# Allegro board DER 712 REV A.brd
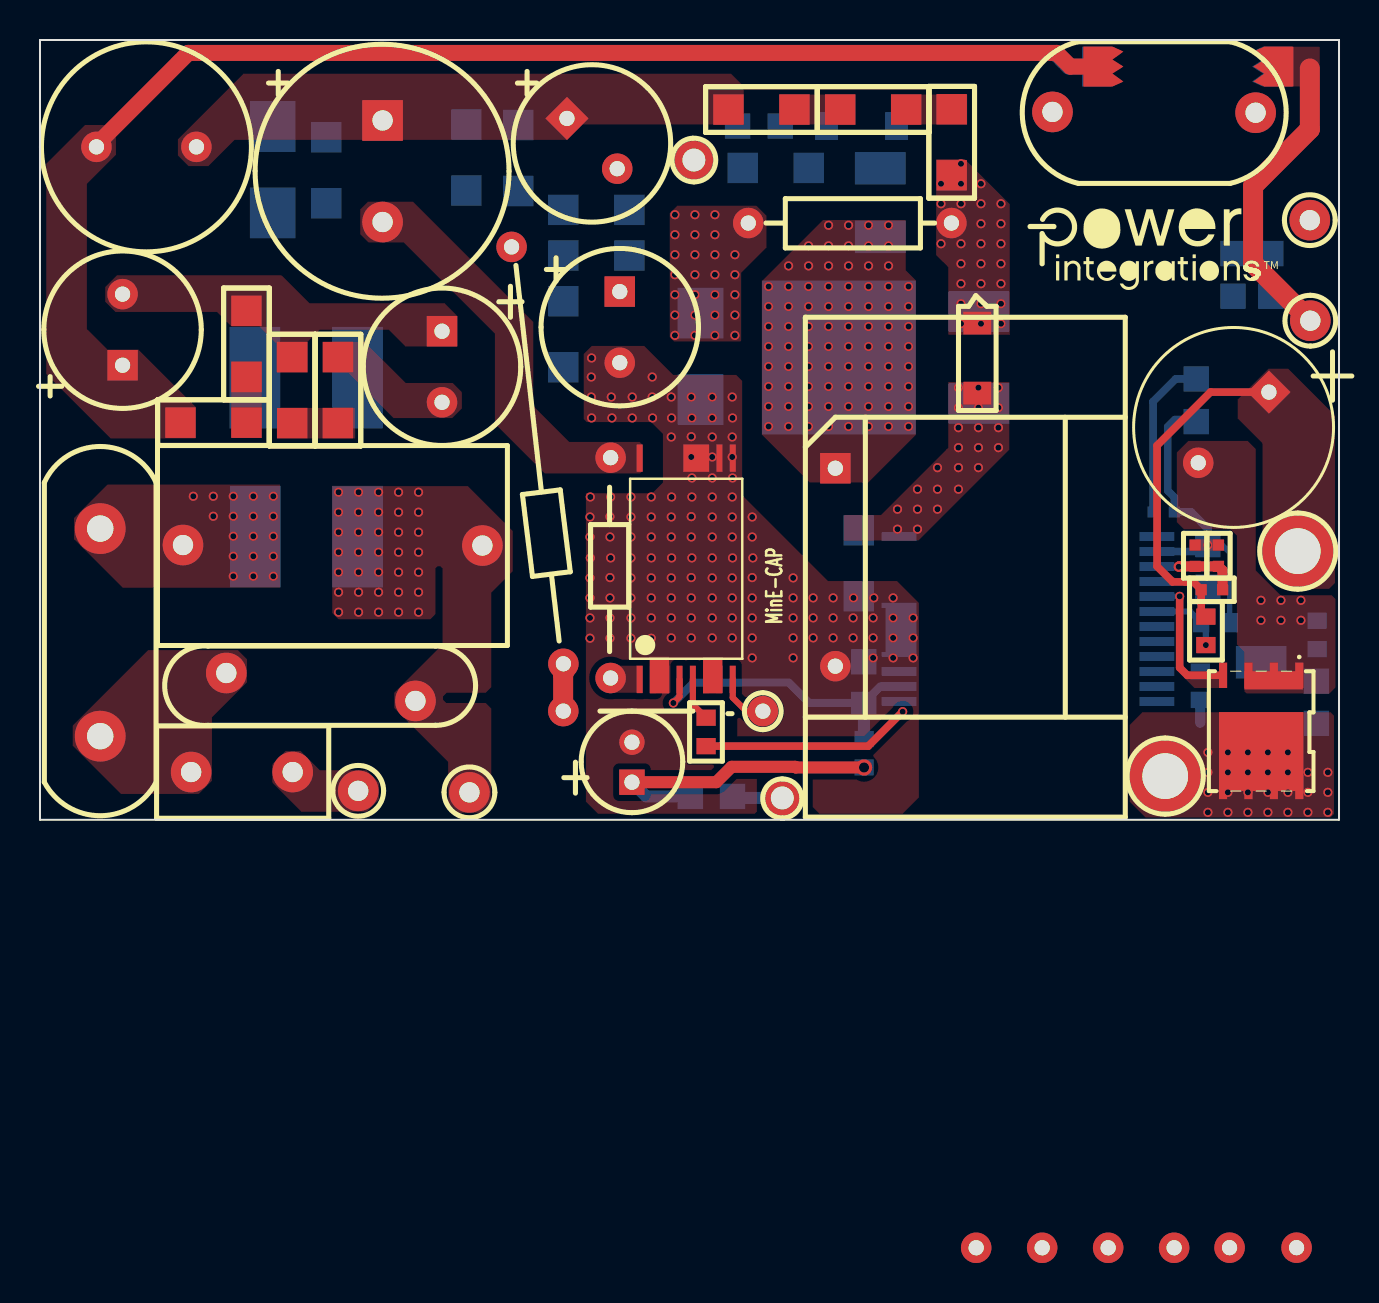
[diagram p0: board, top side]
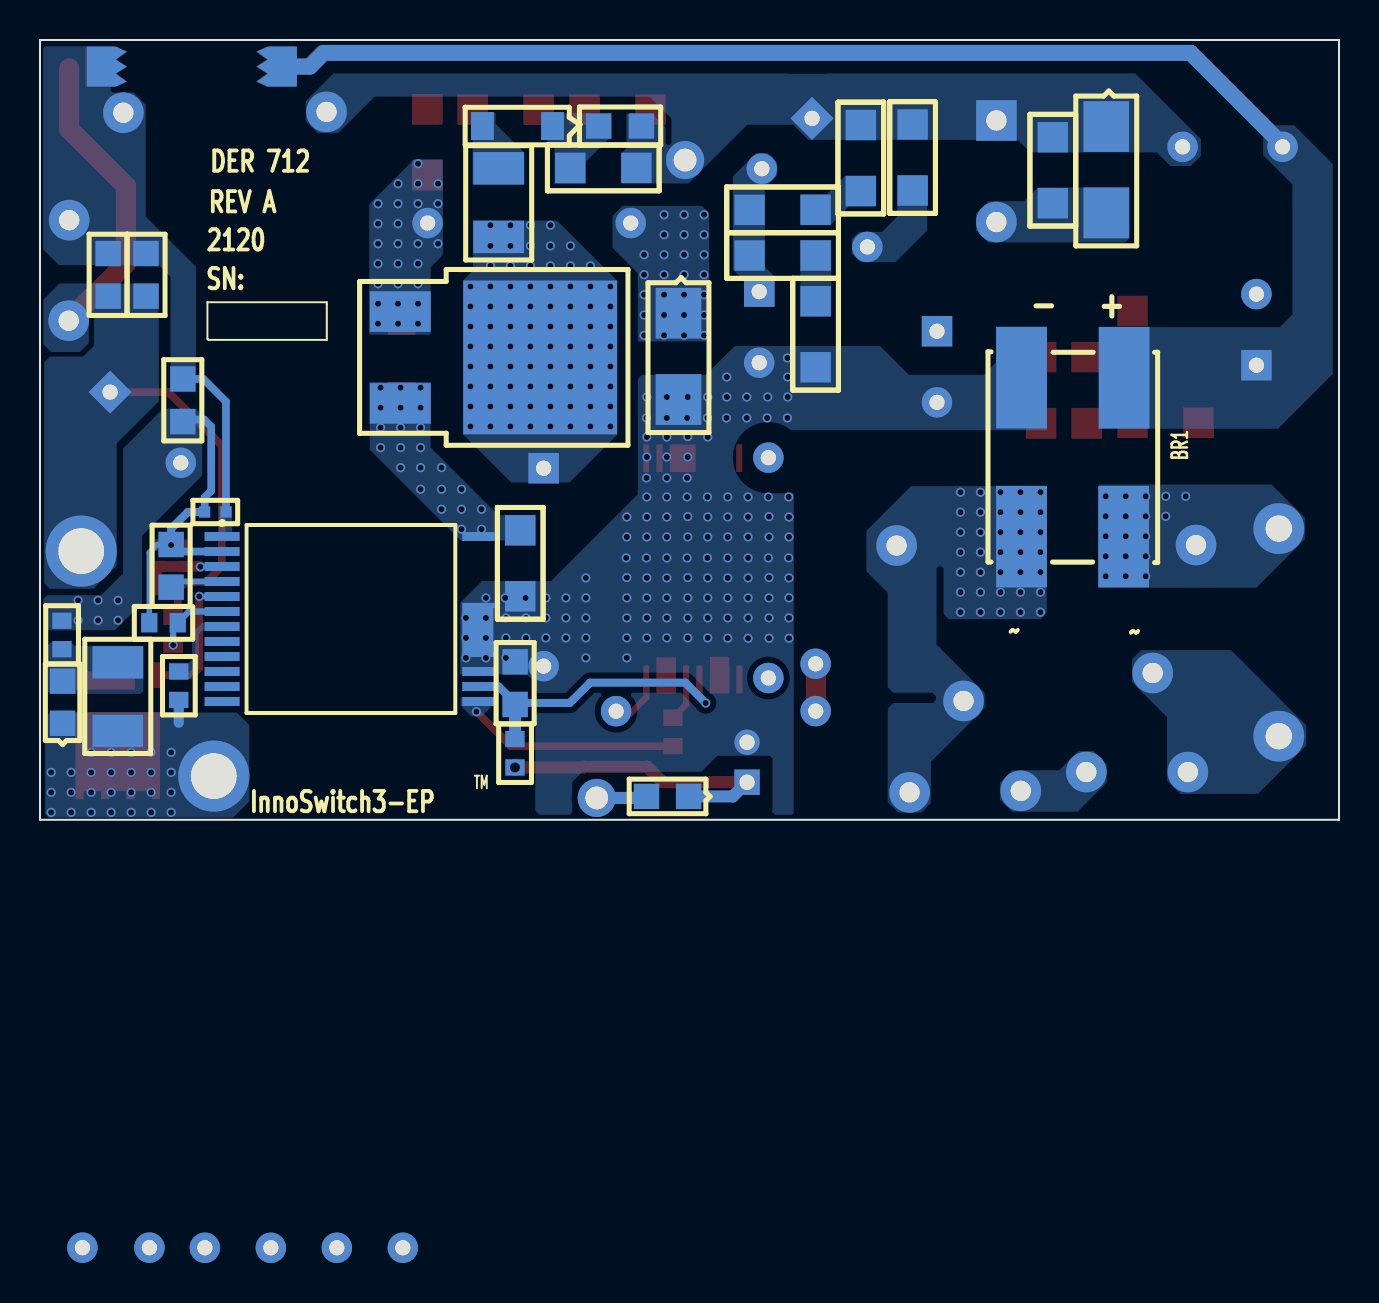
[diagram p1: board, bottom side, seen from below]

Outline 64.97 x 39 mm; copper layers: TOP, BOTTOM. Coordinates in mm from the lower left corner of the outline.
Outline path: 0,39 0,0 64.97,0 64.97,39 0,39

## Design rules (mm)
constraint set DEFAULT: min track width 0.508

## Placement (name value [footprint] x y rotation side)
BR1  Z4DGP410L-HF  [PI_SM_D_Z4D]  10.77 22.16 180 bottom
C1  0.1 uF  [PI_NP_CAP_RAD_17P5X10XLS15D040]  7.13 13.72 0 top
C2  22 uF  [PIPOLCAPCLYD320LS140030]  4.13 22.73 90 top
C3  1 nF  [PINPYCAPRAD540X290LS400040]  50.64 36.65 0 top
C4  1000 pF  [PISMC0805]  34.89 34.7 0 bottom
C6  4.7 uF  [PISMC0805]  41.21 5.77 90 bottom
C7  1000 pF  [PISMC0603]  63.87 8.53 90 bottom
C8  1000 uF  [PIPOLCAPCLYD10MMD30]  61.46 21.39 225 top
C10  2.2 uF  [PISMC0805]  58.41 11.63 90 bottom
C11  1 uF  [PISMC0603]  59.5 9.86 180 bottom
C12  1000 pF  [PISMR0402]  56.73 15.39 180 bottom
C13  1000 pF  [PISMR0402]  57.77 13.74 270 top
C16  10 uF  [PISMC0805]  61.56 26.19 90 bottom
C17  10 uF  [PISMC0805]  59.67 26.19 90 bottom
C18  22 uF  [PIPOLCAPCLYD320LS140030]  26.35 35.08 315 top
C19  82 uF  [PIPOLCAPCLYD500LS200040]  17.13 34.98 270 top
C21  22 uF  [PIPOLCAPCLYD200LS80030]  29.61 1.88 90 top
C24  22 uF  [PIPOLCAPCLYD320LS140030]  20.11 24.43 270 top
C25  22 uF  [PIPOLCAPCLYD320LS140030]  29 26.42 270 top
C27  22 pF  [PISMC1206]  40.95 14.48 270 bottom
D1  SM4007PL-TP  [PI_SM_SOD-123_12]  39.33 34.7 0 bottom
D2  BAV20WS-7-F  [PISMDSOD323]  32.53 1.17 0 bottom
D4  BAV20WS-7-F  [PISMDSOD323]  63.84 4.83 90 bottom
F1  5 A  [PI_RST_MICROFUSE]  12.64 2.39 180 top
FL1  Hole_70mils  [PI_HOLE_70MIL]  62.91 13.41 0 top
FL2  Hole_70mils  [PI_HOLE_70MIL]  56.28 2.16 0 top
FL3  Hole_30mils  [PI_HOLE_30MIL]  37.12 1.09 0 top
FL4  Hole_30mils  [PI_HOLE_30MIL]  32.7 32.99 0 top
GND  BLK  [PITPKEYSTONE100X100]  63.51 29.99 270 top
L  BLK  [PITPKEYSTONE100X100]  15.92 1.45 90 top
L1  220 uH  [PICHOKE10P5X14P5D030]  5.32 33.66 0 top
N  WHT  [PITPKEYSTONE100X100]  21.48 1.37 90 top
NOREF  -  []  -223.63 -144.78 0 top
NOREF#2  -  []  0 0 0 top
NOREF#3  -  []  49.47 30.38 0 top
NOREF#4  -  []  -145.82 54.23 0 top
NOREF#5  -  []  0 0 90 top
Q2  AON6220  [PISMPQFN5X6B]  62.98 7.23 180 top
Q3  STD15N50M2AG  [PISMDDPAK]  46.95 25.42 270 bottom
R3  1.6 M  [PI18WVRESD80LS100D030#2]  23.59 28.65 270 top
R5  20  [PISMR1210]  42.03 32.58 270 bottom
R7  470 k  [PISMR1206]  35.14 32.6 0 bottom
R8  4.7 k  [PISMR0603]  41.21 2.62 90 bottom
R11  8.2  [PISMR1210]  61.08 4.45 90 bottom
R12  47  [PISMR0603]  58.03 5.99 90 bottom
R15  100.0 k  [PISMR0402]  58.08 11.51 0 top
R16  5.62 k  [PISMR0402]  58.94 12.67 90 top
R24  3.9 M  [PISMR1206]  14.32 34.14 270 bottom
R27  1.3 M  [PI18WVRESD80LS100D030]  28.54 20.11 270 top
R28  10  [PI14WVRESD100LS100D030]  45.58 29.84 180 top
R29  1.6 M  [PISMR1206]  21.33 34.77 270 bottom
R30  1 M  [PISMR1206]  45.6 35.53 270 top
R31  1 M  [PISMR1206]  40.02 35.52 0 top
R32  1 M  [PISMR1206]  34.43 35.52 0 top
R33  0.012  [PISMR0805]  57.83 22.05 270 bottom
R34  10 M  [PISMR1206]  7.03 19.86 0 top
R35  10 M  [PISMR1206]  10.33 22.15 90 top
R36  10 M  [PISMR1206]  12.61 23.14 270 top
R37  10 M  [PISMR1206]  14.9 19.84 90 top
R38  10 M  [PISMR1206]  23.92 34.75 270 bottom
R39  10 M  [PISMR1206]  26.18 30.51 0 bottom
R40  10 M  [PISMR1206]  29.48 28.22 180 bottom
R41  10 M  [PISMR1206]  26.18 25.93 270 bottom
R42  20 k  [PISMR0603]  33.31 5.11 270 top
R43  1.6 M  [PI18WVRESD80LS100D030#3]  27.66 5.44 0 top
R44  100  [PISMR0603]  58.31 8.74 90 top
RT1  10  [PI_RAD770X220LS330D052]  3.01 13.56 270 top
RV1  440 VAC  [PIDISC610X212LS295X95040]  10.3 7.85 0 top
SG1  6.5 mm gap  [PI_SPARK_GAP_6P5MM]  57.37 37.67 0 bottom
SG2  6.5 mm gap  [PI_SPARK_GAP_6P5MM]  57.43 37.67 0 top
T2  ATQ25/16  [PI_BOBBIN_ATQ25_H_8P]  46.28 12.63 0 top
U1  INN3679C-H606  [PI_IC_INSOP_24D]  55.86 14.17 180 bottom
U4  MIN1072M  [PI_SM_MINSOP16A_1]  29.99 7.02 0 top
UNK24V  RED  [PITPKEYSTONE100X100]  63.53 24.96 0 top
VR1  MMSZ5246B-7-F  [PI_SM_SOD-123_12]  46.88 24.84 270 top
VR2  SMAJ400A  [PISMDO214AC12]  33.03 25.34 270 bottom
VR4  BZG03C200-M3-08  [PISMDO214AC12]  11.64 34.67 270 bottom

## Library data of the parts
BR1 = DISCRETE BRIDGE_+~~-
C1 = CAP NP: alternate symbols: (pi_np_cap_rad_17p5x10xLS15d040H)
C2 C18 C24 C25 = CAP POL: alternate symbols: (pipolcapclyd320ls140030h630)
C3 = CAP NP: alternate symbols: (pinpycaprad540x290ls400040h,pinpycaprad500x220ls400040)
C4 C6 C7 C10 C27 = CAP NP
C8 = CAP POL: alternate symbols: (pipolcapclyd10x18mmD30H)
C11 = CAP NP: alternate symbols: (pismc0603_1)
C12 C13 = CAP NP: alternate symbols: (pismr0402_1); room: 2
C16 C17 = CAP NP: alternate symbols: (pismc0805_1)
C19 = CAP POL: alternate symbols: (pipolcapclyd500ls200040850lh)
C21 = CAP POL: alternate symbols: (pipolcapclyd5p0x11mms2p0d30h)
D1 D2 D4 = DIODE
F1 = FUSE: alternate symbols: (pirstmicrofusehoz)
FL1-FL4 = FlyingLead: room: 2
GND L = TESTPOINT: alternate symbols: (TP_TH_CR2_D1_1)
L1 = INDUCTOR: alternate symbols: (pichoke10p5x14p5d030H)
N UNK24V = TESTPOINT
Q2 = FET_N_SGD_123_4_5678
Q3 = FET_N_GDS: alternate symbols: (pi_sm_d_pak_1)
R3 R27 R43 = R: alternate symbols: (pi18wresd080ls300d030)
R5 R7 R8 R11 R16 R24 R29-R42 R44 = R
R12 = R: alternate symbols: (pismr0603_1); room: 2
R15 = R: alternate symbols: (pismr0402_1)
R28 = R: alternate symbols: (pi14wvresd100ls125d030,pi14wvresd100ls150d030,pi14wvresd100ls200d030,pi14wvresd100ls300d030,pi14wresd100ls400d030,pi14wresd100ls500d030)
RT1 = THERMISTOR
RV1 = VARISTOR
SG1 SG2 = SPARK_GAP
T2 = BATQ25_8P/GENERIC
U1 = Inno3EP_P15
U4 = MinE-CAP
VR1 VR2 VR4 = DIODE_ZENER

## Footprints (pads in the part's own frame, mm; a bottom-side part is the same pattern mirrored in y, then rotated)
PI14WVRESD100LS100D030
  round 1.524 hole 0.762: 1(0,0) 2(10.16,0)
PI18WVRESD80LS100D030
  round 1.524 hole 0.762: 1(2,0) 2(13.02,0)
PI18WVRESD80LS100D030#2
  round 1.524 hole 0.762: 1(0,0) 2(20.849,2.591)
PI18WVRESD80LS100D030#3
  round 1.524 hole 0.762: 1(-1.484,0) 2(8.497,-0.004)
PI_BOBBIN_ATQ25_H_8P
  rect 1.524x1.524 hole 0.762: 1(-6.5,4.95)
  round 1.524 hole 0.762: 2(13.216,-34.032) 3(16.567,-34.032) 4(-6.5,-4.95) 5(10.443,-34.037) 6(7.143,-34.037) 7(3.843,-34.037) 8(0.543,-34.037)
PI_HOLE_30MIL
  round 1.905 hole 1.143: 1(0,0)
PI_HOLE_70MIL
  round 3.556 hole 2.286: 1(0,0.025)
PI_IC_INSOP_24D
  rect 1.75x0.45 smd: 1(0,0) 2(0,-0.75) 3(0,-1.5) 4(0,-2.25) 5(0,-3) 6(0,-3.75) 7(0,-4.5) 8(0,-5.25) 9(0,-6) 10(0,-6.75) 11(0,-7.5) 12(0,-8.25) 13(12.89,-8.25) 14(12.89,-7.5) 15(12.89,-6.75) 24(12.89,0)
  custom 0.438x0.438 smd: 16(12.89,-4.67)
PI_NP_CAP_RAD_17P5X10XLS15D040
  round 2.032 hole 1.016: 1(0.025,0.025) 2(15,0)
PI_RAD770X220LS330D052
  round 2.54 hole 1.321: 1(-1,0) 2(9.382,0)
PI_RST_MICROFUSE
  round 2.032 hole 1.016: 1(0,0) 2(5.08,0)
PI_SM_D_Z4D
  rect 2.54x5.08 smd: 1(0.025,-0.051) 2(0,-8.001) 3(-5.105,-8.001) 4(-5.105,-0.051)
PI_SM_MINSOP16A_1
  rect 0.3x1.37 smd: 1(0,0) 2(0.665,0) 3(1.33,0) 4(1.995,0) 5(2.66,0) 6(3.325,0) 7(3.99,0) 8(4.655,0) 9(4.655,11.067) 10(3.99,11.067) 16(0,11.067)
  rect 1.292x1.37 smd: 11(2.829,11.067)
PI_SM_SOD-123_12
  rect 1.143x1.397 smd: 1(0,0) 2(3.505,0)
PI_SPARK_GAP_6P5MM
  custom 0.5x0.5 smd: 1(-4.25,0) 2(4.25,0)
PICHOKE10P5X14P5D030
  round 1.524 hole 0.762: 1(-2.5,0) 2(2.5,0)
PIDISC610X212LS295X95040
  round 2.032 hole 1.016: 1(-0.984,-0.508) 2(8.477,-1.905)
PINPYCAPRAD540X290LS400040
  round 2.032 hole 1.016: 1(0,-1.25) 2(10.16,-1.29)
PIPOLCAPCLYD10MMD30
  rect 1.524x1.524 hole 0.762: 1(0,0)
  round 1.524 hole 0.762: 2(5,0)
PIPOLCAPCLYD200LS80030
  rect 1.27x1.27 hole 0.762: 1(0,0)
  round 1.27 hole 0.762: 2(2,0)
PIPOLCAPCLYD320LS140030
  rect 1.524x1.524 hole 0.762: 1(0,0)
  round 1.524 hole 0.762: 2(3.556,0)
PIPOLCAPCLYD500LS200040
  rect 2.032x2.032 hole 1.016: 1(0,0)
  round 2.032 hole 1.016: 2(5.08,0)
PISMC0603
  rect 0.813x0.965 smd: 1(0,0) 2(1.422,0)
PISMC0805
  rect 1.27x1.27 smd: 1(0,0) 2(2.134,0)
PISMC1206
  rect 1.524x1.524 smd: 1(0,0) 2(3.302,0)
PISMDDPAK
  rect 2.032x3.048 smd: 1(0.005,0) 3(4.6,0)
  rect 7.699x7.699 smd: 2(2.301,7)
PISMDO214AC12
  rect 2.54x2.286 smd: 1(0,0) 2(4.318,0)
PISMDSOD323
  rect 1.27x1.27 smd: 1(0,0) 2(2.108,0)
PISMPQFN5X6B
  rect 0.406x1.27 smd: 1(0,0) 2(1.27,0) 3(2.54,0) 4(3.81,0)
  rect 0.406x1.219 smd: 5(3.81,5.588) 6(2.54,5.588) 7(1.27,5.588) 8(0,5.588)
PISMR0402
  rect 0.559x0.559 smd: 1(0,0) 2(1.067,0)
PISMR0603
  rect 0.813x0.965 smd: 1(0,0) 2(1.422,0)
PISMR0805
  rect 1.27x1.27 smd: 1(0,0) 2(2.134,0)
PISMR1206
  rect 1.524x1.524 smd: 1(0,0) 2(3.302,0)
PISMR1210
  rect 1.626x2.54 smd: 1(0,0) 2(3.429,0)
PITPKEYSTONE100X100
  round 2.032 hole 1.016: 1(0,0)

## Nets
GND: C7.2 C8.2 C10.2 C11.1 C12.1 C13.1 Q2.1 Q2.2 Q2.3(S3) R16.2 R33.2 U1.2
GND_SIGNAL: C3.2 C12.2 C16.2 C17.2 GND.1 R33.1 SG1.2 U1.1
D: D4.1 FL2.1 Q2.5 Q2.6 Q2.7 Q2.8 R11.1 R12.1
NC8: U1.8
NC9: U1.9
NC10: U1.10
NC11: U1.11
NC12: U1.12
P_GND: BR1.4 C6.2 C21.2 C24.2 C25.2 C27.2 R37.2 R41.2 T2.4 U1.15 U1.16 U4.3 U4.9 U4.10 U4.11 VR2.2
V-PIN: R42.2 U1.13(VPIN)
VTOP: R43.2 U4.8
N10806149: C6.1 R8.2 U1.14 U4.4
N10840366: BR1.1 C2.1 L1.1 R34.1 SG1.1 SG2.1
N10873526: R12.2 U1.7
N10896401: C8.1 C16.1 C17.1 FL1.1 R15.1 R44.2 SG2.2 UNK24V.1
N10897256: C13.2 R15.2 R16.1 U1.3
N10950053: C21.1 D2.1 R8.1
N10961861: C3.1 C4.1 C18.1 C19.1 FL4.1 L1.2 R7.1 R24.1 R29.1 R32.1 R38.1 VR4.1
N11099981: BR1.2 C1.1 RT1.1
N11100037: BR1.3(AC2) C1.2 N.1 RV1.2
N11139529: C4.2 D1.1 R7.2
N11156493: C7.1 D4.2 R11.2
N12473754: C19.2 R24.2 R27.1 U4.16 VR4.2
N12475155: C2.2 C24.1 R35.2 R36.1
N12496023: Q2.4 U1.5
N12509564: Q3.2 R5.2 T2.1
N12515315: D1.2 R5.1
N12525421: F1.1 L.1
N12527964: D2.2 FL3.1
N12537489: R27.2 U4.1
N12548420: F1.2 RT1.2 RV1.1
N12550156: C18.2 C25.1 R39.2 R40.1
N12551012: C27.1 Q3.3(S) U1.24 VR1.2
N12551028: Q3.1 R28.1 R30.2 VR1.1
N12554391: R30.1 R31.2
N12554414: R31.1 R32.2
N12556866: R34.2 R35.1
N12556885: R36.2 R37.1
N12557063: R38.2 R39.1
N12557132: R40.2 R41.1
N12568337: R42.1 U4.5
N12586127: R28.2 VR2.1
N12588091: R3.2 R43.1
N12588138: R3.1 R29.2
N12597786: C10.1 U1.4
N12598687: C11.2 R44.1 U1.6

Pads without a net: T2 2 3 5 6 7 8; U4 2 6 7

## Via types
v1: diameter 0.457, hole 0.305, TOP to BOTTOM, 371 vias
v2: diameter 0.813, hole 0.508, TOP to BOTTOM, 1 via

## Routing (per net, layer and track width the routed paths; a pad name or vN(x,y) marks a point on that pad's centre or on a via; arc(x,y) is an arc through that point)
GND: length 16.1
  BOTTOM w0.27: C11.1 59.5,13.36 59.1,13.77 C10.2
  BOTTOM w0.381: C10.2 58.06,13.42 55.86,13.42 U1.2 ; C12.1 56.73,16.13 56.4,16.46 56.4,19.66 56.76,20.01 57.73,20.01
  BOTTOM w0.4: C10.2 58.41,14.55 57.58,15.39 57.47,15.39 57.47,15.39 C12.1
  vias: v1(58.41,13.74) v1(61.06,10.98) v1(61.06,9.98) v1(62.06,10.98) v1(62.06,9.98) v1(63.06,10.98) v1(63.06,9.98)
GND_SIGNAL: length 8.2
  BOTTOM w0.381: C12.2 55.67,20.91 56.8,22.05 R33.1
  BOTTOM w0.4: C12.2 55.67,15.39 55.69,15.39
D: length 1.1
  BOTTOM w0.508: R12.1 58.03,4.85
  vias: v1(58.41,3.37) v1(58.41,2.37) v1(58.41,1.37) v1(58.41,0.37) v1(59.41,3.37) v1(59.41,2.37) v1(59.41,1.37) v1(59.41,0.37) v1(60.41,3.37) v1(60.41,2.37) v1(60.41,1.37) v1(60.41,0.37) v1(61.41,3.37) v1(61.41,2.37) v1(61.41,1.37) v1(61.41,0.37) v1(62.41,3.37) v1(62.41,2.37) v1(62.41,1.37) v1(62.41,0.37) v1(63.41,2.37) v1(63.41,1.37) v1(63.41,0.37) v1(64.41,2.37) v1(64.41,1.37) v1(64.41,0.37)
P_GND:
  vias: v1(27.51,15.15) v1(27.51,14.15) v1(27.51,12.1) v1(27.51,11.1) v1(27.51,10.1) v1(27.51,9.08) v1(27.59,23.1) v1(27.57,22.14) v1(27.57,21.14) v1(27.59,20.1) v1(27.52,16.15) v1(27.52,13.1) v1(28.51,15.16) v1(28.51,14.15) v1(28.51,12.11) v1(28.51,11.1) v1(28.51,10.1) v1(28.51,9.08) v1(28.57,21.14) v1(28.6,20.1) v1(28.54,16.15) v1(28.54,13.1) v1(29.56,16.15) v1(29.56,15.15) v1(29.56,14.15) v1(29.56,13.1) v1(29.56,12.1) v1(29.56,11.1) v1(29.56,10.1) v1(29.56,9.08) v1(29.62,21.14) v1(29.62,20.1) v1(30.57,16.15) v1(30.57,15.15) v1(30.57,14.15) v1(30.57,13.1) v1(30.57,12.1) v1(30.57,11.1) v1(30.57,10.1) v1(30.57,9.08) v1(30.62,22.14) v1(30.62,21.14) v1(30.64,20.1) v1(31.57,21.14) v1(31.59,20.1) v1(31.57,19.14) v1(31.59,16.15) v1(31.57,15.15) v1(31.57,14.15) v1(31.59,13.1) v1(31.57,12.1) v1(31.57,11.1) v1(31.57,10.1) v1(31.57,9.1) v1(32.57,21.14) v1(32.6,20.1) v1(32.57,19.16) v1(32.57,18.14) v1(32.6,17.1) v1(32.6,16.15) v1(32.57,15.16) v1(32.57,14.15) v1(32.6,13.1) v1(32.57,12.11) v1(32.57,11.1) v1(32.57,10.1) v1(32.57,9.1) v1(33.62,21.14) v1(33.62,20.1) v1(33.62,19.14) v1(33.62,18.14) v1(33.62,17.1) v1(33.62,16.15) v1(33.62,15.15) v1(33.62,14.15) v1(33.62,13.1) v1(33.62,12.1) v1(33.62,11.1) v1(33.62,10.1) v1(33.62,9.1) v1(34.62,21.14) v1(34.64,20.1) v1(34.62,19.14) v1(34.62,18.14) v1(34.64,17.1) v1(34.62,16.15) v1(34.62,15.15) v1(34.62,14.15) v1(34.64,13.1) v1(34.62,12.1) v1(34.62,11.1) v1(34.62,10.1) v1(34.62,9.1) v1(35.62,15.15) v1(35.62,14.15) v1(35.65,13.1) v1(35.62,12.11) v1(35.62,11.1) v1(35.62,10.1) v1(35.62,9.1) v1(35.62,8.1) v1(37.67,12.1) v1(37.67,11.1) v1(37.67,10.1) v1(37.67,9.1) v1(37.67,8.1) v1(38.67,11.1) v1(38.67,10.1) v1(38.67,9.1) v1(39.67,11.1) v1(39.67,10.1) v1(39.67,9.1) v1(40.68,11.1) v1(40.67,10.1) v1(40.67,9.1) v1(41.7,11.1) v1(41.67,10.1) v1(41.67,9.1) v1(41.67,8.1) v1(42.67,11.1) v1(42.67,10.1) v1(42.67,9.1) v1(42.67,8.1) v1(43.67,10.1) v1(43.67,9.1) v1(43.67,8.1)
V-PIN: length 10.5
  TOP w0.381: v1(43.14,5.41) 41.42,3.68 R42.2
VTOP: length 2.8
  TOP w0.305: R43.2 36.03,5.3 35.45,5.3 34.65,6.11 U4.8
N10806149: length 15.8
  TOP w0.305: U4.4 31.99,6.16 31.97,6.14 31.97,6.13 v1(31.68,5.84)
  BOTTOM w0.4: 43.14,6.67 U1.14 42.03,6.67 41.21,5.84 C6.1 41.13,5.84 38.47,5.84 37.45,6.86 32.69,6.86 v1(31.68,5.84)
  BOTTOM w0.6: C6.1 41.21,4.05 R8.2
N10840366: length 105.2
  TOP w0.8: SG2.1 51.53,37.67 50.85,38.35 7.42,38.35 2.77,33.71
  BOTTOM w0.8: 2.77,33.71 7.42,38.35 50.78,38.35 51.46,37.67 SG1.1
N10896401: length 31.9
  TOP w0.381: R44.2 58.08,10.39 R15.1 57.68,11.9 57.27,11.9 56.64,11.9 55.87,12.67 55.87,18.72 58.54,21.39 C8.1
  TOP w1: 63.51,37.57 63.51,34.54 60.67,31.7 60.67,27.82 UNK24V.1
N10897256: length 4.3
  TOP w0.508: v1(56.95,12.65) 56.97,12.67 C13.2 57.91,12.67 R16.1 59.14,12.47 R15.2
  BOTTOM w0.27: v1(56.95,12.65) 56.94,12.67 U1.3
N10950053: length 15.2
  TOP w0.6: v2(41.21,2.62) 37.8,2.62 37.77,2.65 34.59,2.65 33.82,1.88 C21.1
  BOTTOM w0.6: D2.1 30.32,1.17 C21.1
N11099981:
  vias: v1(7.67,16.18) v1(8.67,16.18) v1(8.67,15.18) v1(9.67,16.18) v1(9.67,15.18) v1(9.67,14.18) v1(9.67,13.18) v1(9.67,12.18) v1(10.67,16.18) v1(10.67,15.18) v1(10.67,14.18) v1(10.67,13.18) v1(10.67,12.18) v1(11.67,16.18) v1(11.67,15.18) v1(11.67,14.18) v1(11.67,13.18) v1(11.67,12.18)
N11100037:
  vias: v1(14.93,16.38) v1(14.93,15.38) v1(14.93,14.38) v1(14.93,13.38) v1(14.93,12.38) v1(14.93,11.38) v1(14.93,10.38) v1(15.93,16.38) v1(15.93,15.38) v1(15.93,14.38) v1(15.93,13.38) v1(15.93,12.38) v1(15.93,11.38) v1(15.93,10.38) v1(16.93,16.38) v1(16.93,15.38) v1(16.93,14.38) v1(16.93,13.38) v1(16.93,12.38) v1(16.93,11.38) v1(16.93,10.38) v1(17.93,16.38) v1(17.93,15.38) v1(17.93,14.38) v1(17.93,13.38) v1(17.93,12.38) v1(17.93,11.38) v1(17.93,10.38) v1(18.93,16.38) v1(18.93,15.38) v1(18.93,14.38) v1(18.93,13.38) v1(18.93,12.38) v1(18.93,11.38) v1(18.93,10.38)
N12496023: length 7
  TOP w0.381: v1(57,11.18) 57,7.61 57.38,7.23 Q2.4
  BOTTOM w0.27: v1(57,11.18) 56.99,11.17 U1.5
N12509564:
  vias: v1(36.44,26.67) v1(36.44,25.67) v1(36.44,24.67) v1(36.44,23.67) v1(36.44,22.67) v1(36.44,21.67) v1(36.44,20.67) v1(36.44,19.67) v1(37.44,27.7) v1(37.44,26.67) v1(37.44,25.67) v1(37.44,24.67) v1(37.44,23.67) v1(37.44,22.67) v1(37.44,21.67) v1(37.44,20.67) v1(37.44,19.67) v1(38.44,28.7) v1(38.44,27.7) v1(38.44,26.67) v1(38.44,25.67) v1(38.44,24.67) v1(38.44,23.67) v1(38.44,22.67) v1(38.44,21.67) v1(38.44,20.67) v1(38.44,19.67) v1(39.44,29.73) v1(39.44,28.7) v1(39.44,27.7) v1(39.44,26.67) v1(39.44,25.67) v1(39.44,24.67) v1(39.44,23.67) v1(39.44,22.67) v1(39.44,21.67) v1(39.44,20.67) v1(39.44,19.67) v1(40.44,29.73) v1(40.44,28.7) v1(40.44,27.7) v1(40.44,26.67) v1(40.44,25.67) v1(40.44,24.67) v1(40.44,23.67) v1(40.44,22.67) v1(40.44,21.67) v1(40.44,20.67) v1(40.44,19.67) v1(41.44,29.73) v1(41.44,28.7) v1(41.44,27.7) v1(41.44,26.67) v1(41.44,25.67) v1(41.44,24.67) v1(41.44,23.67) v1(41.44,22.67) v1(41.44,21.67) v1(41.44,20.67) v1(41.44,19.67) v1(42.44,29.73) v1(42.44,28.7) v1(42.44,27.7) v1(42.44,26.67) v1(42.44,25.67) v1(42.44,24.67) v1(42.44,23.67) v1(42.44,22.67) v1(42.44,21.67) v1(42.44,20.67) v1(42.44,19.67) v1(43.44,26.67) v1(43.44,25.67) v1(43.44,24.67) v1(43.44,23.67) v1(43.44,22.67) v1(43.44,21.67) v1(43.44,20.67) v1(43.44,19.67)
N12527964: length 2.5
  BOTTOM w0.6: FL3.1 34.71,1.09 D2.2
N12551012:
  vias: v1(42.89,15.53) v1(42.89,14.53) v1(43.89,16.53) v1(43.89,15.53) v1(43.89,14.53) v1(44.89,17.61) v1(44.89,16.53) v1(44.89,15.53) v1(45.93,21.61) v1(45.93,20.61) v1(45.93,19.61) v1(45.93,18.61) v1(45.93,17.61) v1(45.93,16.53) v1(46.93,21.61) v1(46.93,20.61) v1(46.93,19.61) v1(46.93,18.61) v1(46.93,17.61) v1(47.93,21.61) v1(47.93,20.61) v1(47.93,19.61) v1(47.93,18.61)
N12551028:
  vias: v1(45.06,31.81) v1(45.06,30.81) v1(45.06,28.81) v1(46.06,32.81) v1(46.06,31.81) v1(46.06,30.81) v1(46.06,28.81) v1(46.06,27.81) v1(46.06,26.81) v1(46.06,25.81) v1(46.06,24.81) v1(47.06,31.81) v1(47.06,30.81) v1(47.06,29.81) v1(47.06,28.81) v1(47.06,27.81) v1(47.06,26.81) v1(47.06,25.81) v1(47.06,24.81) v1(48.06,30.81) v1(48.06,29.81) v1(48.06,28.81) v1(48.06,27.81) v1(48.06,26.81) v1(48.06,25.81) v1(48.06,24.81)
N12568337: length 2.2
  TOP w0.305: R42.1 32.65,5.77 U4.5
N12586127:
  vias: v1(31.76,30.26) v1(31.76,29.26) v1(31.76,28.26) v1(31.76,27.26) v1(31.76,26.26) v1(31.76,25.24) v1(31.76,24.23) v1(32.76,30.26) v1(32.76,29.26) v1(32.76,28.26) v1(32.76,27.26) v1(32.76,26.26) v1(32.76,25.24) v1(32.76,24.23) v1(33.76,30.26) v1(33.76,29.26) v1(33.76,28.26) v1(33.76,27.26) v1(33.76,26.26) v1(33.76,25.24) v1(33.76,24.23) v1(34.76,28.26) v1(34.76,27.26) v1(34.76,26.26) v1(34.76,25.24) v1(34.76,24.23)
N12588091: length 2.9
  TOP w1: R43.1 26.16,5.44 26.16,7.29 26.18,7.3 ; 26.18,7.3 R3.2 26.18,7.3
N12597786: length 2.7
  BOTTOM w0.27: U1.4 58.13,11.92 C10.1
N12598687: length 3.7
  BOTTOM w0.305: U1.6 57.52,10.42 C11.2 58.31,9.63 v1(58.31,8.74)

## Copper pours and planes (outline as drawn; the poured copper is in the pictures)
GND on TOP (solid shape): 63.16,6.52 60.24,6.52 60.24,7.43 63.16,7.43
GND on TOP: 60.81,12.47 60.81,18.55 60.4,18.95 57.44,18.95 57.22,18.73 56.86,18.37 56.86,14.89 57.22,14.53 59.54,14.53 59.86,14.21 59.86,8.77 60.24,8.39 60.24,6.43 60.35,6.31 64.49,6.31 64.79,6.62 64.79,11.04 64.61,11.23 63.36,11.23 62.05,11.23
GND on BOTTOM: 61.22,9.48 64.52,9.48 64.79,9.75 64.79,11.05 64.61,11.23 61.9,11.23 60.81,12.33 60.81,18.57 58.82,20.56 57.18,20.56 56.86,20.24 56.86,17.21 59.73,14.34 59.86,14.2 59.86,10.84
GND_SIGNAL on BOTTOM: 59.02,27.74 64.02,27.74 64.81,28.52 64.81,38.58 64.71,38.68 61.53,38.68 61.43,38.58 61.43,36.47 61.33,36.37 60.29,36.37 59.68,35.76 59.68,30.18 57.16,27.66 57.16,21.41 58.43,21.41 58.43,27.15
GND_SIGNAL on BOTTOM: 55.36,15.7 55.36,13.97 56,13.97 56,15.7
D on TOP (solid shape): 63.18,1.44 58.97,1.44 58.97,5.39 63.18,5.39
D on TOP: 64.72,0.3 64.54,0.12 55.29,0.12 54.5,0.91 54.5,4.74 55.14,5.38 64.55,5.38 64.72,5.21
D on BOTTOM: 55.3,0.11 64.3,0.11 64.32,0.1 64.53,0.1 64.71,0.28 64.71,5.11 64.45,5.37 55.13,5.37 54.5,4.74 54.5,0.91
P_GND on TOP (solid shape): 31.46,6.32 30.49,6.32 30.49,8.15 31.46,8.15
P_GND on TOP (solid shape): 34.13,6.32 33.16,6.32 33.16,8.13 34.13,8.13
P_GND on TOP: 18.29,21.84 20.64,21.84 21.1,21.39 21.1,20.57 20.61,20.09 17.68,20.09 15.39,22.38 14.19,22.38 14.16,22.4 14.16,23.9 16.23,23.9
P_GND on TOP: 43.96,10.85 42.86,11.94 40.05,11.94 40.04,11.94 39.41,11.94 35.12,16.23 35.12,21.95 34.81,22.25 32.53,22.25 31.66,22.25 30.22,23.7 27.6,23.7 27.19,23.29 27.19,20.04 27.35,19.89 30.57,19.89 31.16,19.3 31.16,16.87 30.62,16.33 27.3,16.33 27.3,0.91 27.91,0.31 35.75,0.31 35.85,0.41 35.85,2.01 36.26,2.41 38.19,2.41 38.65,1.95 38.65,0.64 38.98,0.3 43.14,0.3 43.96,1.12 ; 1 cut-out
P_GND on BOTTOM: 14.61,24.66 17.14,24.66 17.15,24.66 17.15,22.88 17.78,22.25 20.35,22.25 20.36,22.25 21.51,22.25 22.95,23.7 30.22,23.7 31.66,22.25 34.86,22.25 35.07,22.05 35.07,16.28 39.39,11.95 39.39,11.94 42.86,11.94 43.96,10.85 43.96,7.26 40.6,7.26 40.2,6.86 40.2,0.46 39.99,0.25 38.47,0.25 38.34,0.38 38.34,1.89 37.84,2.4 31.89,2.4 31.09,3.2 28.46,3.2 28.34,3.07 28.34,0.48 28.36,0.46 28.36,0.41 28.21,0.25 27.37,0.25 27.27,0.36 27.27,16.31 27.29,16.33 28.49,16.33 28.54,16.33 30.32,18.11 28.54,19.89 27.94,19.78 27.41,19.48 14.61,19.48
V-PIN on BOTTOM: 42.36,5.69 42.36,6.12 43.93,6.12 43.93,5.71 43.39,5.18 42.87,5.18
N10840366 on TOP: 3.53,19.08 0.31,22.3 0.31,32.8 2.26,34.75 3.17,34.75 3.8,34.12 3.8,33.26 2.35,31.8 2.35,24.54 3.37,23.52 4.92,23.52 7.79,20.65 7.79,19.08
N10840366 on BOTTOM: 9.97,19.56 3.05,19.56 0.39,22.22 0.31,22.3 0.31,32.8 0.39,32.88 2.25,34.74 3.16,34.74 3.79,34.11 3.79,33.24 2.33,31.78 2.33,25.27 2.97,24.64 11.99,24.64 12.01,24.61 12.01,19.56 9.97,19.56
N10873526 on BOTTOM: 55.08,9.86 55.08,9.47 56.71,9.47 56.71,9.47 56.85,9.47 57.04,9.28 57.04,7.51 57.55,7.01 58.51,7.01 58.51,7.82 57.54,7.82 57.36,8.01 57.36,9.34 56.85,9.86
N10896401 on TOP: 61.44,22.56 60.29,21.41 59.9,21.01 59.9,20.08 61.14,18.84 61.14,12.71 62.29,11.55 64.47,11.55 64.77,11.84 64.77,20.22 64.64,20.34 62.43,22.56
N10896401 on TOP: 64,36.68 64,38.66 61.43,38.66 61.43,36.68
N10896401 on BOTTOM: 62.29,11.55 64.47,11.55 64.76,11.84 64.76,22.86 64.46,23.16 62.82,23.16 62.27,23.71 62.27,25.23 62.32,25.29 62.45,25.29 62.52,25.21 62.52,23.85 62.97,23.39 64.41,23.39 64.8,23.78 64.8,26.02 63.99,26.82 59.03,26.82 59.03,26.83 59.03,20.93 61.13,18.83 61.13,12.71
N10961861 on TOP: 35.19,34.77 35.19,36.68 34.56,37.31 25.01,37.31 23.69,37.31 10.17,37.31 6.9,34.04 6.9,33.22 7.43,32.69 8.42,32.69 9.73,34 26.36,34 27.12,34.77
N10961861 on BOTTOM: 32.53,31.83 35.85,31.83 35.88,31.8 35.88,33.35 35.64,33.59 35.64,35.31 34.36,35.31 33.68,34.63 33.68,33.85 33.59,33.76 33.47,33.76 33.39,33.83 33.39,35.08 34.48,36.17 48.22,36.17 50.05,34.34 51.07,34.34 51.68,34.95 51.68,35.94 50.29,37.33 27.55,37.33 27.54,37.32 25.6,37.32 25.59,37.33 10.19,37.33 6.9,34.03 6.9,33.21 7.41,32.7 8.43,32.7 9.1,33.38 15.45,33.38 16.08,34.01 26.54,34.01 27.3,34.76 29.59,34.76
N11099981 on TOP: 1.7,15.1 1.7,14.04 4.13,11.61 12,11.61 12,11.61 12,16.76 3.37,16.76
N11099981 on BOTTOM: 12,11.61 4.13,11.61 1.7,14.03 1.7,15.1 3.37,16.76 12,16.76
N11100037 on TOP: 14.62,16.69 14.62,10.34 14.93,10.03 19.52,10.03 19.78,10.28 19.78,12.57 19.88,12.67 20.03,12.67 20.13,12.57 20.13,8.76 17.72,6.35 17.72,5.59 20.41,2.9 20.41,0.86 20.92,0.36 22.01,0.36 22.57,0.91 22.57,5.56 22.29,5.84 20.31,5.84 20.16,5.99 20.16,6.17 20.33,6.35 22.29,6.35 22.57,6.63 22.57,11.35 23.64,12.42 23.64,14.45 21.4,16.69
N11100037 on BOTTOM: 20.89,0.36 22.04,0.36 22.57,0.89 22.57,5.56 22.29,5.84 20.31,5.84 20.16,5.99 20.16,6.17 20.33,6.35 22.29,6.35 22.57,6.63 22.57,11.35 23.64,12.42 23.64,14.45 21.4,16.69 14.62,16.69 14.62,10.34 14.92,10.03 19.52,10.03 19.78,10.29 19.78,12.57 19.88,12.67 20.03,12.67 20.13,12.57 20.13,8.76 17.72,6.35 17.72,5.59 20.41,2.9 20.41,0.84
N11139529 on BOTTOM: 37.68,32.89 37.68,31.8 39.23,31.8 39.23,33.58 39.84,34.19 39.84,35.33 36.51,35.33 36.51,34.06
N11156493 on BOTTOM: 64.61,6.45 64.61,8.69 64.41,8.89 63.43,8.89 63.22,8.68 59.81,8.68 59.8,8.68 59.8,6.44 59.94,6.3 64.45,6.3
N12473754 on TOP: 18.65,30.91 23.67,25.9 24.67,24.9 24.67,20.69 26.46,18.9 29.99,18.9 30.11,18.77 30.11,17.42 30.01,17.32 25.25,17.32 24.25,18.32 22.75,19.82 22.75,24.31 21.94,25.13 18.19,28.87 16.43,28.87 16.02,29.29 16.02,30.53 16.4,30.91
N12473754 on BOTTOM: 15.06,31.62 10.48,31.62 10.48,29.09 10.7,28.87 17.55,28.87 18.15,29.47 18.15,30.32 17.54,30.93 15.75,30.93
N12475155 on TOP: 11.83,22.38 13.38,22.38 13.38,23.9 13.98,24.51 17.44,24.51 18.28,23.67 20.82,23.67 20.84,23.7 20.84,25.22 20.23,25.83 13.48,25.83 12.08,27.23 3.85,27.23 3.27,26.64 3.27,25.91 3.77,25.4 8.85,25.4 9.57,24.69 10.96,24.69 11.83,23.83
N12496023 on TOP: 59.37,7.39 59.37,6.61 59.38,6.59 57.73,6.59 57.24,7.09 57.24,7.24 57.42,7.42 59.34,7.42
N12509564 on TOP: 36.11,26.95 36.11,19.25 38.5,16.87 41.42,16.87 43.8,19.25 43.8,26.97 43.3,27.48 43.3,29.97 43.27,30 39.16,30
N12509564 on BOTTOM: 43.8,26.97 43.8,19.28 41.39,16.87 38.49,16.87 36.12,19.24 36.11,19.24 36.11,26.97 39.11,29.97 43.3,29.97 43.31,29.96 43.31,27.47
N12515315 on BOTTOM: 43.33,35.36 43.33,31.79 43.32,31.78 40.76,31.78 40.76,33.38 42.18,34.8 42.18,35.36
N12525421 on TOP: 11.62,2.78 11.62,1.85 13.07,0.41 16.35,0.41 16.96,1.02 16.96,1.85 16.33,2.48 14,2.48 13.03,3.44 12.28,3.44
N12525421 on BOTTOM: 11.62,1.85 13.07,0.41 16.35,0.41 16.96,1.02 16.96,1.85 16.33,2.48 14,2.48 13.03,3.44 12.28,3.44 11.62,2.78
N12537489 on TOP: 30.12,7.71 30.12,6.35 28.57,6.35 28.45,6.47 28.45,7.6 28.55,7.71
N12548420 on TOP: 5.41,8.48 1.64,4.71 1.64,3.71 4.05,1.29 7.94,1.29 8.6,1.96 8.6,5.13 10.35,6.88 10.35,8.03 9.9,8.48
N12548420 on BOTTOM: 7.94,1.3 8.6,1.96 8.6,5.13 10.35,6.88 10.35,8.03 9.9,8.48 5.4,8.48 1.64,4.72 1.64,3.71 4.05,1.3
N12550156 on BOTTOM: 28.71,27.66 28.23,27.17 28.23,25.65 29.73,25.65 29.76,25.68 29.76,26.97 30.32,27.53 30.32,32.17 29.63,32.86 29.16,33.33 28.56,33.33 28.2,32.98 28.2,32.97 28.11,32.87 28.11,32.21 28.71,31.6
N12551012 on TOP: 45.43,21.89 48.48,21.89 48.48,18.52 43.93,13.97 40.2,13.97 40.2,15.21 40.22,15.24 42.05,15.24 45.43,18.62
N12551012 on BOTTOM: 45.43,18.62 42.05,15.24 40.22,15.24 40.2,15.21 40.2,13.97 43.93,13.97 43.96,13.99 48.48,18.51 48.48,21.89 45.43,21.89
N12551028 on TOP: 44.82,33.05 46.24,33.05 48.5,30.78 48.5,24.26 45.43,24.26 45.43,27.64 44.82,28.24
N12551028 on BOTTOM: 44.82,28.24 45.43,27.64 45.43,24.28 45.46,24.26 48.45,24.26 48.5,24.31 48.5,30.78 46.24,33.04 44.82,33.04 44.82,30.19
N12554391 on TOP: 42.56,36.27 42.56,34.77 46.37,34.77 46.37,36.27
N12554414 on TOP: 36.97,36.27 36.97,34.77 40.78,34.77 40.78,36.27
N12556866 on TOP: 9.57,19.1 11.09,19.1 11.09,22.91 9.57,22.91
N12556885 on TOP: 12,20.6 12,19.08 15.76,19.08 15.76,20.6
N12557063 on BOTTOM: 23.16,32.2 23.16,30.83 23.33,30.67 24.52,30.67 25.44,29.74 26.94,29.74 26.94,31.27 25.64,31.27 24.7,32.2 23.17,32.2
N12557132 on BOTTOM: 25.39,28.98 25.39,25.17 26.94,25.17 26.94,28.98
N12586127 on TOP: 35.07,27.36 36.34,28.63 36.34,30.2 35.83,30.71 31.87,30.71 31.5,30.34 31.5,24.14 31.71,23.93 35.04,23.93 35.07,23.95
N12586127 on BOTTOM: 35.83,30.71 36.34,30.2 36.34,28.6 35.07,27.33 35.07,23.95 35.04,23.92 31.72,23.92 31.5,24.14 31.5,30.34 31.87,30.71
N12588138 on BOTTOM: 20.6,32.23 20.6,29.47 21.87,28.2 22.18,27.89 23.94,27.89 24.37,28.32 24.37,29.03 24.01,29.4 22.86,29.4 22.49,29.77 22.09,30.16 22.09,32.23 20.6,32.23

Small or netless copper shapes (teardrops, artwork), in the pictures only: 1 on TOP

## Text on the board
Ref Des/Silkscreen Bottom: TM | InnoSwitch3-EP | DER 712 | REV A | 2120 | SN:
Ref Des/Silkscreen Top: MinE-CAP
User.6: NOTES: PLEASE DELETE | 14.  FAB HOUSE LOGO,DATE CODE TO BE IN SILK SCREEN ONLY.DO NOT USE COPPER. | 13.  MATERIAL FR4 COPPER 2oz THICKNESS 0.039"
User.8: FIGURE | FINISHED_SIZE | 12.0 | 20.0 | 30.0 | 40.0 | 45.0 | 52.0 | 90.0 | DRILL CHART: TOP to BOTTOM | ALL UNITS ARE IN MILS | TOLERANCE_DRILL | +3.0/-3.0 | PLATED | QTY | 371 | 1 | 28 | 2 | 12
